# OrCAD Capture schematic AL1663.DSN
size D; title: AL1663 - UNIVERSAL FLYBACK AND BUCK-BOOST SINGLE STAGE DIMMABLE; rev: 1.0; note: DS38466 Rev. 2 - 2
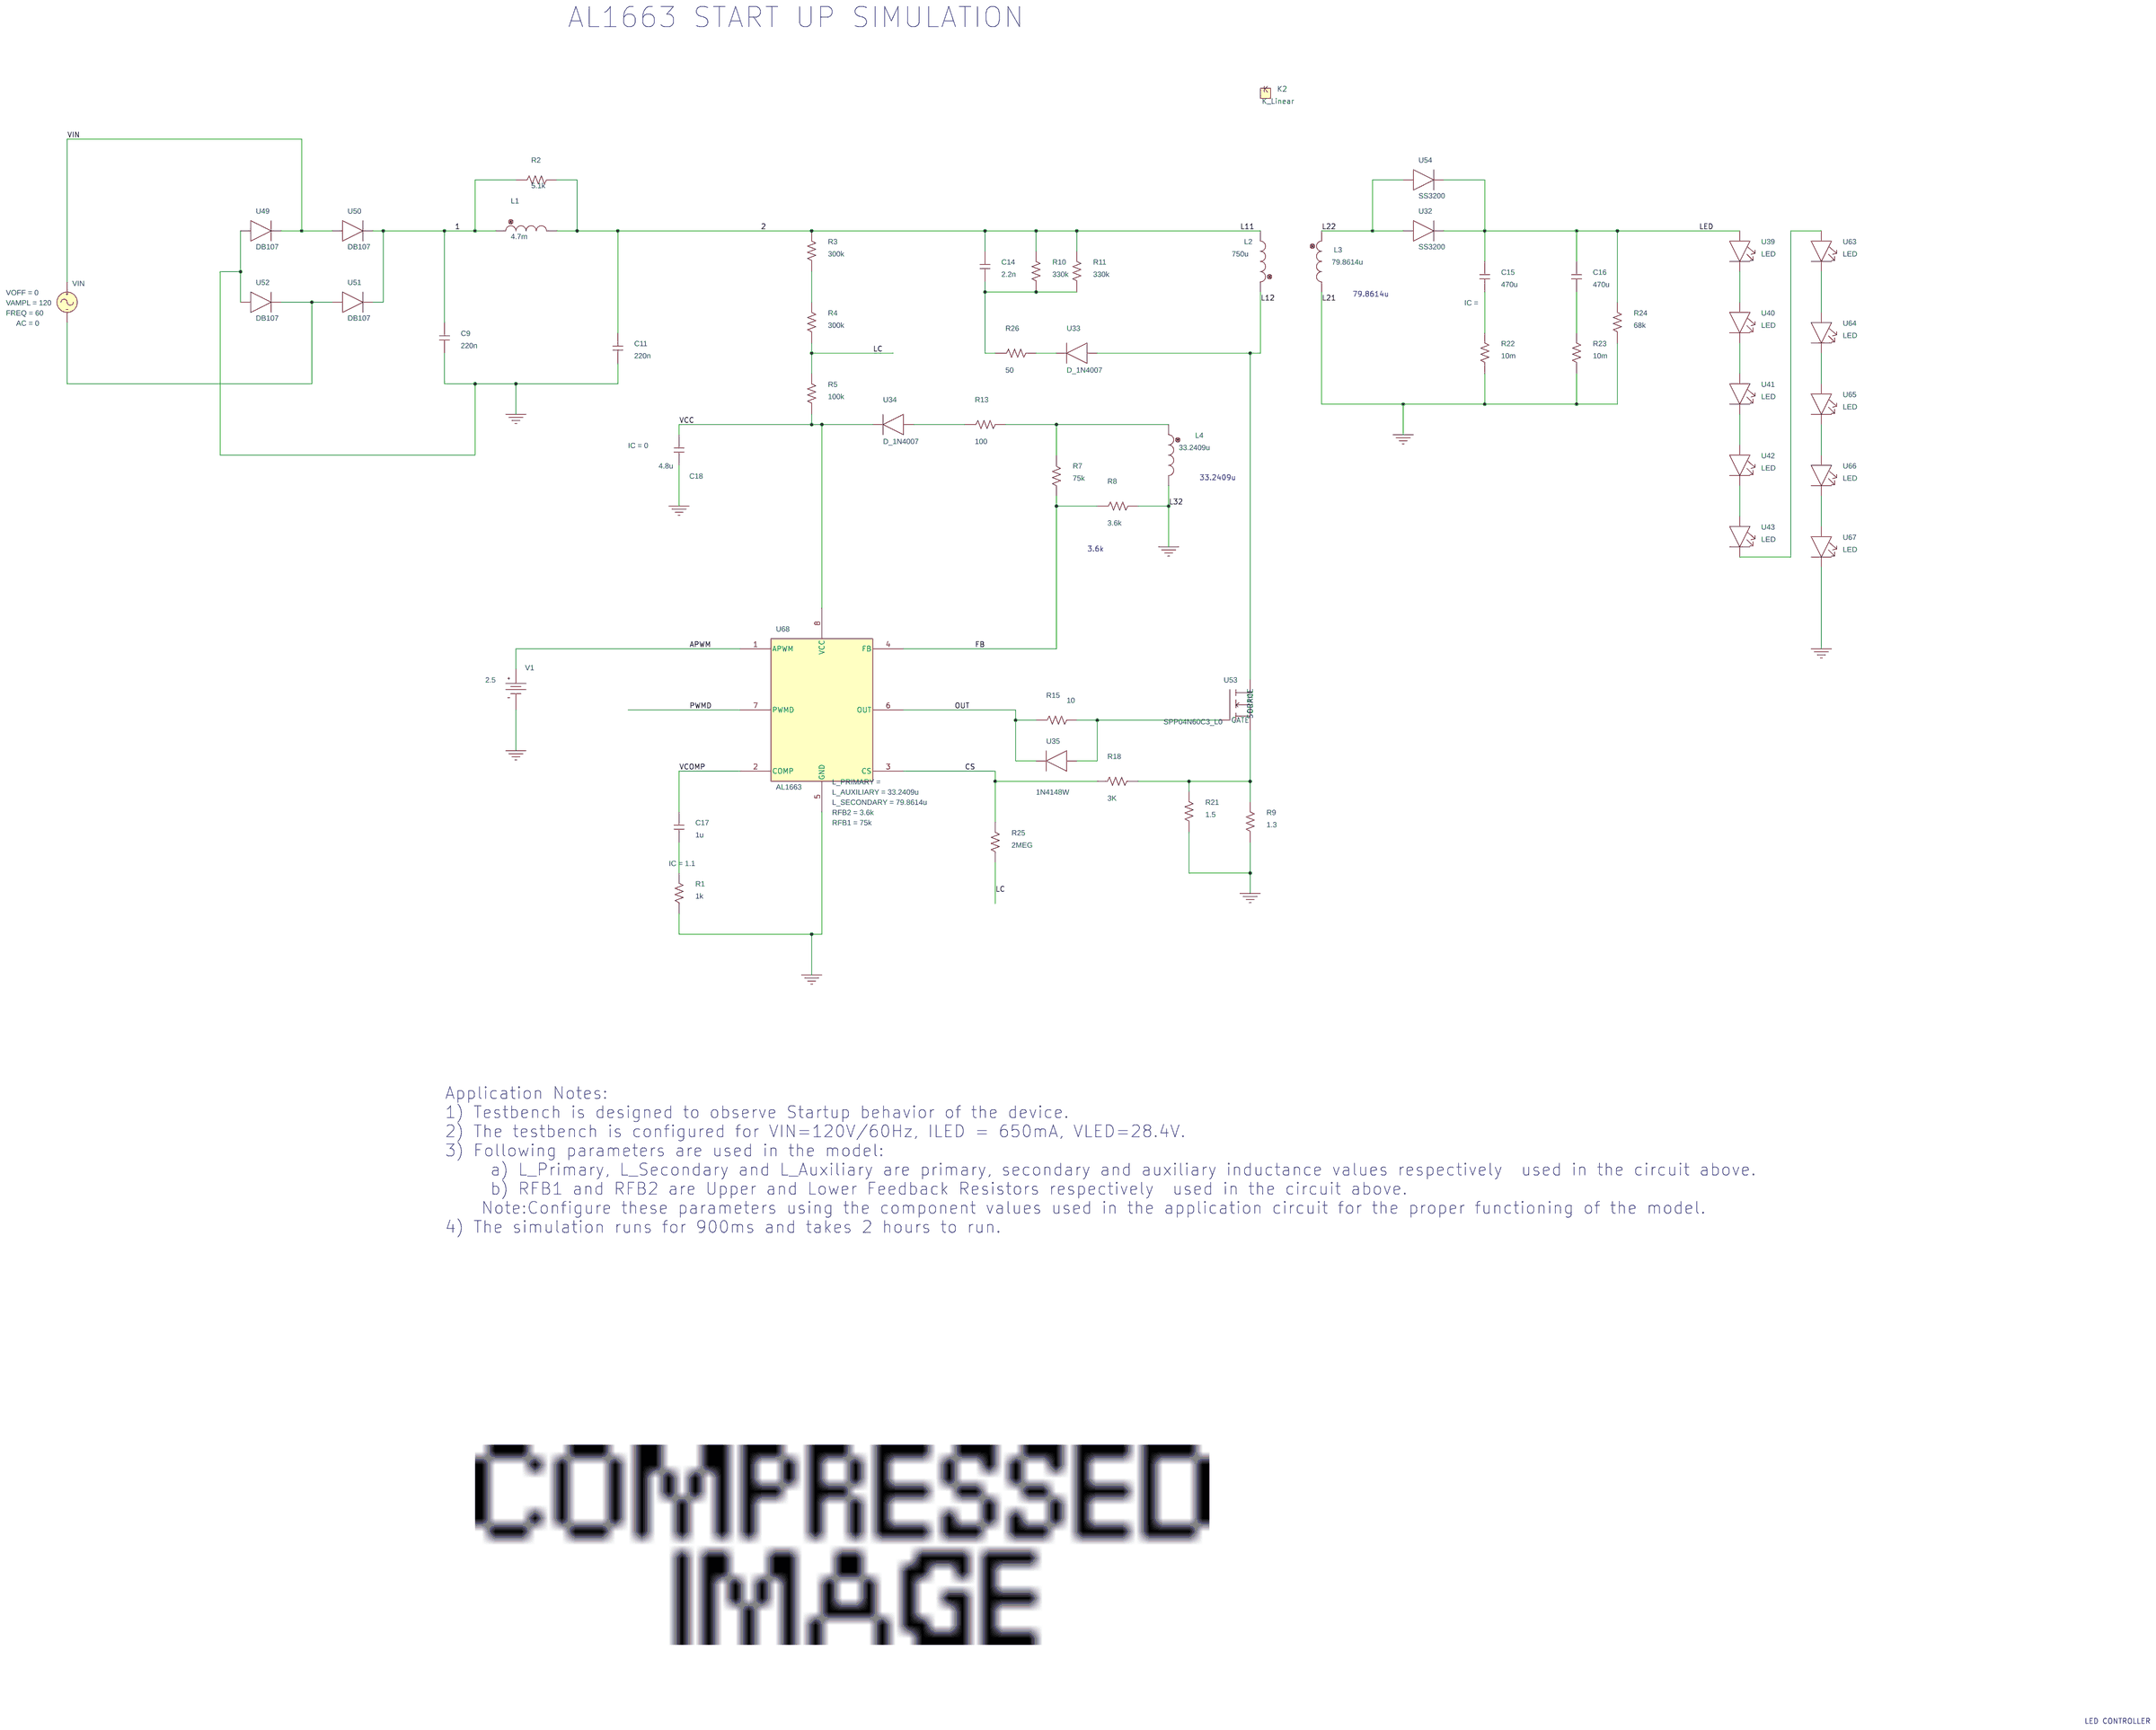
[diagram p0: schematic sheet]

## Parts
C9  220n  [RAD/CK05]
C11  220n  [RAD/CK05]
C14  2.2n  [RAD/CK05]
C15  470u  [RAD/CK05]
C16  470u  [RAD/CK05]
C17  1u  [RAD/CK05]
C18  4.8u  [RAD/CK05]
K2  K_Linear
L1  4.7m  [DISC/.350x.175/LS.200x.100/.034]
L2  750u  [DISC/.350x.175/LS.200x.100/.034]
L3  79.8614u  [DISC/.350x.175/LS.200x.100/.034]
L4  33.2409u  [DISC/.350x.175/LS.200x.100/.034]
R1  1k  [AX/RC05]
R2  5.1k  [AX/RC05]
R3  300k  [AX/RC05]
R4  300k  [AX/RC05]
R5  100k  [AX/RC05]
R7  75k  [AX/RC05]
R8  3.6k  [AX/RC05]
R9  1.3  [AX/RC05]
R10  330k  [AX/RC05]
R11  330k  [AX/RC05]
R13  100  [AX/RC05]
R15  10  [AX/RC05]
R18  3K  [AX/RC05]
R21  1.5  [AX/RC05]
R22  10m  [AX/RC05]
R23  10m  [AX/RC05]
R24  68k  [AX/RC05]
R25  2MEG  [AX/RC05]
R26  50  [AX/RC05]
U32  SS3200
U33  D_1N4007
U34  D_1N4007
U35  1N4148W
U39  LED
U40  LED
U41  LED
U42  LED
U43  LED
U49  DB107
U50  DB107
U51  DB107
U52  DB107
U53  SPP04N60C3_L0
U54  SS3200
U63  LED
U64  LED
U65  LED
U66  LED
U67  LED
U68  AL1663
V1  VDC
VIN  VSIN

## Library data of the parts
C9 C11 C14-C16 = C
C17 = C: IC: 1.1
C18 = C: IC: 0
K2 = K_Linear: COUPLING: 0.999; L1: L2; L2: L3; L3: L4
L1 L4 = L
L2 L3 = L: IL1: 0
R1-R5 R7-R11 R13 R15 R18 R21-R26 = R
U32 U54 = SS3200
U33 U34 = D_1N4007
U35 = 1N4148W
U39-U43 U63-U67 = LED
U49-U52 = DB107
U53 = SPP04N60C3_L0
U68 = AL1663: L_AUXILIARY: 33.2409u; L_SECONDARY: 79.8614u; RFB1: 75k; RFB2: 3.6k
V1 = VDC: DC: 2.5
VIN = VSIN: AC: 0; AppProp: Sine$Voltage$0$-1; DC: 0; FREQ: 60; VAMPL: 120; VOFF: 0

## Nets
VCC: C18.1 R5.1 U34.2 U68.8(VCC)
VIN: U49.2 U50.1 VIN.1(+)
0: C9.1 C11.1 C18.2 L3.2 L4.2 R1.1 R8.2 R9.1 R21.1 R22.1 R23.1 R24.1 U49.1 U52.1 U67.2 U68.5(GND) V1.1(-)
1: C9.2 L1.1 R2.1 U50.2 U51.2
2: C11.2 C14.2 L1.2 L2.2 R2.2 R3.2 R10.2 R11.2
APWM: U68.1(APWM) V1.0(+)
CS: R18.2 R25.2 U68.3(CS)
FB: R7.2 R8.1 U68.4(FB)
L12: L2.1 U33.1 U53.1(DRAIN)
L22: L3.1 U32.1 U54.1
LC: R4.1 R5.2 R25.1
LED: C15.1 C16.1 R24.2 U32.2 U39.1 U54.2
OUT: R15.1 U35.2 U68.6(OUT)
PWMD: U68.7(PWMD)
VCOMP: C17.1 U68.2(COMP)
N471704: U43.2 U63.1
N471896: R3.1 R4.2
N471936: U39.2 U40.1
N471942: U63.2 U64.1
N471948: C14.1 R10.1 R11.1 R26.1
N472060: C15.2 R22.2
N472066: C16.2 R23.2
N472072: U51.1 U52.2 VIN.2(-)
N472312: U40.2 U41.1
N472340: R26.2 U33.2
N472360: U64.2 U65.1
N472550: U41.2 U42.1
N472582: R13.1 U34.1
N472588: L4.1 R7.1 R13.2
N472602: U65.2 U66.1
N472740: U42.2 U43.1
N472772: U66.2 U67.1
N473074: R15.2 U35.1 U53.2(GATE)
N473090: R9.2 R18.1 R21.2 U53.3(SOURCE)
N473310: C17.2 R1.2

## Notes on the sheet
- AL1663 START UP SIMULATION
- 79.8614u
- 33.2409u
- 3.6k
- Application Notes:
  1) Testbench is designed to observe Startup behavior of the device.
  2) The testbench is configured for VIN=120V/60Hz, ILED = 650mA, VLED=28.4V.
  3) Following parameters are used in the model:
       a) L_Primary, L_Secondary and L_Auxiliary are primary, secondary and auxiliary inductance values respectively  used in the circuit above.
       b) RFB1 and RFB2 are Upper and Lower Feedback Resistors respectively  used in the circuit above.
      Note:Configure these parameters using the component values used in the application circuit for the proper functioning of the model.
  4) The simulation runs for 900ms and takes 2 hours to run.
- LED CONTROLLER
